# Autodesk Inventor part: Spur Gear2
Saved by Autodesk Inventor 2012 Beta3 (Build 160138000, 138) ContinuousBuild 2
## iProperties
Created: 2010-12
Part Number: Spur Gear2
Material: Steel
Document SubType Name: Modeling
Designer: Thom Tremblay
Categories: <?xml version="1.0" encoding="UTF-16"?> <MemberInstance><Categories><FamilyTemplate><FamilyTemplateParameter ValueType="xs:double" Id="1" ObjectReferenceKey="da
Density: 1 g/cm^3
CustomPartVersion: 1
Author: Thom Tremblay
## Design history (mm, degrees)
sketch "Sketch1"
  geometry: C1 r 42.825 at (0, 0)
  constraints: 1 centre point
  dimensions: "d0" = 85.64993 diameter of C1 (= da_da)
extrude "Extrusion1" new body sketch "Sketch1" distance "d1" = 12 (= da_b); taper "d2" = 0 deg
workplane "Work Plane2"
sketch "Sketch2"
  geometry: C1 r 42.825 at (0, 0) reference; C2 r 41.837 at (0, 0)
  constraints: 1 centre point, 1 coincident
  dimensions: "d3" = 83.67347 diameter of C2 (= da_dw)
feature "Pitch Diameter" sketch "Sketch2" dims "d4" = 10, "d5" = 0
workplane "Work Plane8"
workplane "Work Plane9"
feature "Spur Gear" dims "da_b" = 12, "da_d" = 82, "da_aw" = 50, "da_da" = 85.64993, "da_df" = 81.29409, "da_dw" = 83.67347, angle "da_beta" = 0 deg, "da_lefttooth" = 0, "da_righttooth" = 0
node "Keyway1"
body "Solid1"
body "Srf1"
feature "Hub Keyway"
other parameters: "d17" = 0, "d34" = 0.38312 (computed from da_z), "d39" = 0, "d41" = 0, "d47" = 0, "d48" = 0
